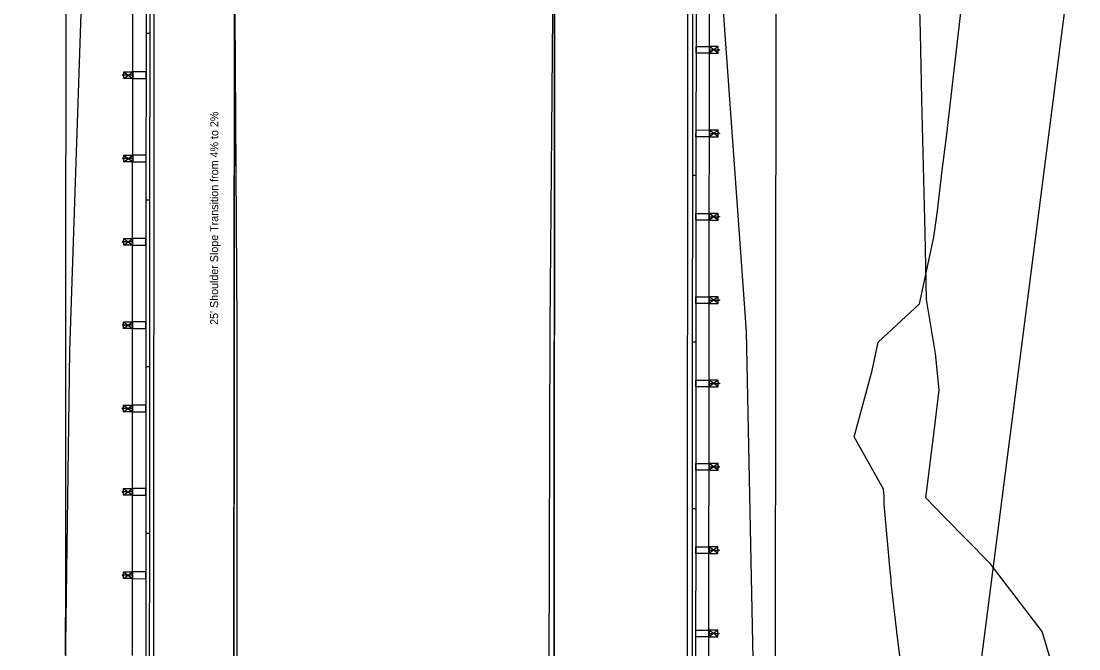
# Model space of a CAD drawing. Extents: x 18543285 to 18543485, y 7434209 to 7435438.
# Drawn here: x 18543356.7 to 18543436, y 7434626.5 to 7434673.5 of the extents above; entities that cross this region are included whole.
import ezdxf

# ---------------------------------------------------------------- set-up
doc = ezdxf.new("R2010")
doc.units = 0
for name, color, linetype in [('_CIVIL_CONSTRUCTION', 7, 'Continuous'), ('Contours Major', 7, 'Continuous'), ('Dimensions', 7, 'Continuous'), ('Draft_1', 7, 'Continuous'), ('EdgeUnpaved', 7, 'Continuous'), ('EXT_SNP', 7, 'Continuous'), ('MeshTop', 7, 'Continuous'), ('Sawcut', 7, 'Continuous'), ('Terrain', 7, 'Continuous'), ('TL_ForeSlope', 7, 'Continuous'), ('TL_Grading', 7, 'Continuous'), ('TL_GroundIntercept', 7, 'Continuous')]:
    doc.layers.add(name, color=color, linetype=linetype)

msp = doc.modelspace()

# ---------------------------------------------------------------- linework, layer by layer
at = {"layer": '_CIVIL_CONSTRUCTION'}
for p, q in [((18543372.717, 7434758.131), (18543372.483, 7434398.131)), ((18543396.702, 7434735.024), (18543396.468, 7434375.024)), ((18543396.468, 7434375.024), (18543442.702, 7434734.994))]:
    msp.add_line(p, q, dxfattribs=at)
at = {"layer": 'Contours Major'}
for p, q in [((18543366.494, 7434414.304), (18543366.721, 7434764.553)), ((18543406.503, 7434428.685), (18543406.706, 7434741.433))]:
    msp.add_line(p, q, dxfattribs=at)
for points in [[(18543365.016, 7434626.011), (18543365.02, 7434631.761), (18543365.02, 7434632.261), (18543365.024, 7434638.011), (18543365.024, 7434638.511), (18543365.056, 7434688.511), (18543365.06, 7434694.261), (18543365.06, 7434694.761), (18543365.065, 7434700.511), (18543365.064, 7434701.011), (18543365.085, 7434732.261), (18543365.086, 7434734.886), (18543365.101, 7434758.323), (18543365.101, 7434758.823), (18543365.134, 7434759.303)], [(18543410.073, 7434448.682), (18543409.662, 7434459.133), (18543409.398, 7434465.002), (18543408.155, 7434496.603), (18543408.262, 7434502.429), (18543408.242, 7434502.929), (18543408.171, 7434508.639), (18543408.179, 7434521.639), (18543408.182, 7434527.389), (18543408.183, 7434527.889), (18543408.268, 7434659.139), (18543408.272, 7434664.889), (18543408.272, 7434665.389), (18543408.301, 7434709.139), (18543408.303, 7434711.764), (18543408.305, 7434714.889), (18543408.305, 7434715.389), (18543408.307, 7434718.014), (18543408.316, 7434732.076), (18543408.317, 7434732.576), (18543408.317, 7434733.639), (18543408.318, 7434735.701), (18543408.286, 7434736.181), (18543408.292, 7434745.597)]]:
    msp.add_lwpolyline(points, dxfattribs=at)
at = {"layer": 'Dimensions'}
for p, q in [((18543424.09, 7434672.685), (18543423.973, 7434677.682)), ((18543424.208, 7434667.687), (18543424.09, 7434672.685)), ((18543424.325, 7434662.69), (18543424.208, 7434667.687)), ((18543424.443, 7434657.692), (18543424.325, 7434662.69)), ((18543424.56, 7434652.695), (18543424.443, 7434657.692)), ((18543425.23, 7434648.632), (18543424.56, 7434652.695)), ((18543425.51, 7434645.922), (18543425.23, 7434648.632)), ((18543425.115, 7434642.783), (18543425.51, 7434645.922)), ((18543424.49, 7434637.824), (18543425.115, 7434642.783)), ((18543425.885, 7434636.402), (18543424.49, 7434637.824)), ((18543429.322, 7434632.897), (18543425.885, 7434636.402)), ((18543433.233, 7434627.79), (18543429.322, 7434632.897)), ((18543434.64, 7434623.023), (18543433.233, 7434627.79))]:
    msp.add_line(p, q, dxfattribs=at)
at = {"layer": 'Draft_1'}
for points in [[(18543384.77, 7434781.083), (18543372.9, 7434787.863), (18543372.96, 7434740.606), (18543372.8, 7434701.585), (18543372.37, 7434691.21), (18543372.62, 7434685.7), (18543372.86, 7434650.748), (18543372.86, 7434601.252), (18543372.78, 7434549.829), (18543372.8, 7434512.681), (18543372.38, 7434462.376), (18543372.39, 7434412.042), (18543372.69, 7434360.71), (18543372.51, 7434311.653), (18543372.28, 7434264.026), (18543372.36, 7434218.914)], [(18543384.77, 7434781.083), (18543396.87, 7434774.205), (18543396.35, 7434740.197), (18543396.71, 7434700.664), (18543396.63, 7434690.476), (18543396.62, 7434685.792), (18543396.31, 7434650.659), (18543396.17, 7434599.128), (18543396.23, 7434549.104), (18543396.51, 7434511.985), (18543396.08, 7434463.739), (18543396.34, 7434410.307), (18543396.46, 7434361.391), (18543396, 7434310.756), (18543396.3, 7434264.052), (18543396.31, 7434218.783)]]:
    msp.add_lwpolyline(points, dxfattribs=at)
at = {"layer": 'EdgeUnpaved'}
for points in [[(18543366.95, 7434783.457), (18543367.08, 7434760.542), (18543365.95, 7434740.647), (18543362.08, 7434701.65), (18543360.3, 7434648.83), (18543359.65, 7434601.121), (18543356.68, 7434548.03), (18543360.21, 7434529.205), (18543361.5, 7434513.228), (18543365.09, 7434461.857), (18543364.63, 7434411.718), (18543364.49, 7434411.599), (18543365.08, 7434359.945), (18543365.18, 7434311.057), (18543365.28, 7434264.086), (18543364.89, 7434219.782)], [(18543403.57, 7434766.239), (18543404.16, 7434742.83), (18543404.19, 7434741.424), (18543407.36, 7434701.476), (18543411.03, 7434650.284), (18543412.11, 7434597.502), (18543415.34, 7434550.136), (18543409.98, 7434511.216), (18543406.99, 7434484.053), (18543407.7, 7434463.358), (18543406.85, 7434409.394), (18543406.22, 7434360.833), (18543406.88, 7434310.123), (18543406.41, 7434263.79), (18543406.74, 7434218.275)]]:
    msp.add_lwpolyline(points, dxfattribs=at)
at = {"layer": 'EXT_SNP'}
msp.add_lwpolyline([(18543366.95, 7434783.457), (18543367.08, 7434760.542), (18543365.95, 7434740.647), (18543362.08, 7434701.65), (18543360.3, 7434648.83), (18543359.65, 7434601.121), (18543356.68, 7434548.03), (18543360.21, 7434529.205), (18543361.5, 7434513.228), (18543365.09, 7434461.857), (18543364.63, 7434411.718), (18543364.49, 7434411.599), (18543365.08, 7434359.945), (18543365.18, 7434311.057), (18543365.28, 7434264.086), (18543364.89, 7434219.782)], dxfattribs=at)
at = {"layer": 'MeshTop'}
for points in [[(18543360.016, 7434626.014), (18543360.02, 7434631.761), (18543360.02, 7434632.262), (18543360.024, 7434638.011), (18543360.024, 7434638.512), (18543360.056, 7434688.514), (18543360.06, 7434694.261), (18543360.06, 7434694.762), (18543360.065, 7434700.511), (18543360.064, 7434701.011), (18543360.085, 7434732.264), (18543360.086, 7434734.889), (18543360.101, 7434758.323), (18543360.101, 7434758.996), (18543360.135, 7434759.477)], [(18543360.016, 7434626.014), (18543360.02, 7434631.761), (18543360.02, 7434632.262), (18543360.024, 7434638.011), (18543360.024, 7434638.512), (18543360.056, 7434688.514), (18543360.06, 7434694.261), (18543360.06, 7434694.762), (18543360.065, 7434700.511), (18543360.064, 7434701.011), (18543360.085, 7434732.264), (18543360.086, 7434734.889), (18543360.101, 7434758.323), (18543360.101, 7434758.996), (18543360.135, 7434759.477)], [(18543360.016, 7434626.014), (18543360.02, 7434631.761), (18543360.02, 7434632.262), (18543360.024, 7434638.011), (18543360.024, 7434638.512), (18543360.056, 7434688.514), (18543360.06, 7434694.261), (18543360.06, 7434694.762), (18543360.065, 7434700.511), (18543360.064, 7434701.011), (18543360.085, 7434732.264), (18543360.086, 7434734.889), (18543360.101, 7434758.323), (18543360.101, 7434758.996), (18543360.135, 7434759.477)], [(18543415.073, 7434448.779), (18543414.657, 7434459.344), (18543414.394, 7434465.213), (18543413.157, 7434496.655), (18543413.264, 7434502.482), (18543413.241, 7434503.058), (18543413.171, 7434508.669), (18543413.179, 7434521.636), (18543413.182, 7434527.383), (18543413.183, 7434527.883), (18543413.268, 7434659.136), (18543413.272, 7434664.883), (18543413.272, 7434665.383), (18543413.301, 7434709.136), (18543413.303, 7434711.76), (18543413.305, 7434714.882), (18543413.305, 7434715.384), (18543413.307, 7434718.011), (18543413.316, 7434732.07), (18543413.317, 7434732.572), (18543413.317, 7434733.637), (18543413.318, 7434735.868), (18543413.286, 7434736.347), (18543413.292, 7434745.594)], [(18543415.073, 7434448.779), (18543414.657, 7434459.344), (18543414.394, 7434465.213), (18543413.157, 7434496.655), (18543413.264, 7434502.482), (18543413.241, 7434503.058), (18543413.171, 7434508.669), (18543413.179, 7434521.636), (18543413.182, 7434527.383), (18543413.183, 7434527.883), (18543413.268, 7434659.136), (18543413.272, 7434664.883), (18543413.272, 7434665.383), (18543413.301, 7434709.136), (18543413.303, 7434711.76), (18543413.305, 7434714.882), (18543413.305, 7434715.384), (18543413.307, 7434718.011), (18543413.316, 7434732.07), (18543413.317, 7434732.572), (18543413.317, 7434733.637), (18543413.318, 7434735.868), (18543413.286, 7434736.347), (18543413.292, 7434745.594)]]:
    msp.add_lwpolyline(points, dxfattribs=at)
at = {"layer": 'Sawcut'}
msp.add_lwpolyline([(18543368.55, 7434414.302), (18543372.494, 7434414.3), (18543372.663, 7434674.434), (18543396.663, 7434674.418), (18543396.486, 7434402.372), (18543399.487, 7434402.37)], dxfattribs=at)
at = {"layer": 'TL_ForeSlope'}
for p, q in [((18543372.494, 7434414.3), (18543372.663, 7434674.434)), ((18543396.486, 7434402.372), (18543396.663, 7434674.418))]:
    msp.add_line(p, q, dxfattribs=at)
at = {"layer": 'TL_Grading'}
for p, q in [((18543366.055, 7434685.135), (18543366.047, 7434672.635)), ((18543366.326, 7434685.135), (18543366.318, 7434672.635)), ((18543407.007, 7434674.515), (18543406.999, 7434662.015)), ((18543407.277, 7434674.515), (18543407.269, 7434662.015)), ((18543366.047, 7434672.635), (18543366.039, 7434660.135)), ((18543366.318, 7434672.635), (18543366.047, 7434672.635)), ((18543366.318, 7434672.635), (18543366.047, 7434672.635)), ((18543366.318, 7434672.635), (18543366.309, 7434660.135)), ((18543407.275, 7434671.139), (18543407.276, 7434671.64)), ((18543407.276, 7434671.64), (18543408.276, 7434671.639)), ((18543408.276, 7434671.639), (18543408.276, 7434671.139)), ((18543408.943, 7434671.639), (18543408.276, 7434671.139)), ((18543408.943, 7434671.139), (18543408.276, 7434671.639)), ((18543408.276, 7434671.389), (18543408.943, 7434671.389)), ((18543409.04, 7434671.388), (18543409.047, 7434671.388)), ((18543408.276, 7434671.139), (18543407.275, 7434671.139)), ((18543364.377, 7434669.761), (18543365.044, 7434669.261)), ((18543364.377, 7434669.261), (18543365.044, 7434669.761)), ((18543365.044, 7434669.761), (18543365.044, 7434669.261)), ((18543366.045, 7434669.76), (18543365.044, 7434669.761)), ((18543366.045, 7434669.26), (18543366.045, 7434669.76)), ((18543364.28, 7434669.512), (18543364.273, 7434669.512)), ((18543365.044, 7434669.511), (18543364.377, 7434669.511)), ((18543365.044, 7434669.261), (18543366.045, 7434669.26)), ((18543407.271, 7434664.889), (18543407.272, 7434665.39)), ((18543408.272, 7434664.889), (18543407.271, 7434664.889)), ((18543407.272, 7434665.39), (18543408.272, 7434665.389)), ((18543408.272, 7434665.389), (18543408.272, 7434664.889)), ((18543408.939, 7434665.389), (18543408.272, 7434664.889)), ((18543408.939, 7434664.889), (18543408.272, 7434665.389)), ((18543408.272, 7434665.139), (18543408.939, 7434665.139)), ((18543409.036, 7434665.138), (18543409.043, 7434665.138)), ((18543364.276, 7434663.262), (18543364.269, 7434663.262)), ((18543364.373, 7434663.511), (18543365.04, 7434663.011)), ((18543364.373, 7434663.011), (18543365.04, 7434663.511)), ((18543365.04, 7434663.261), (18543364.373, 7434663.261)), ((18543365.04, 7434663.511), (18543365.04, 7434663.011)), ((18543366.041, 7434663.51), (18543365.04, 7434663.511)), ((18543366.04, 7434663.01), (18543366.041, 7434663.51)), ((18543365.04, 7434663.011), (18543366.04, 7434663.01)), ((18543406.999, 7434662.015), (18543406.99, 7434649.515)), ((18543406.999, 7434662.015), (18543407.269, 7434662.015)), ((18543406.999, 7434662.015), (18543407.269, 7434662.015)), ((18543407.269, 7434662.015), (18543407.261, 7434649.515)), ((18543366.039, 7434660.135), (18543366.03, 7434647.635)), ((18543366.309, 7434660.135), (18543366.039, 7434660.135)), ((18543366.309, 7434660.135), (18543366.039, 7434660.135)), ((18543366.309, 7434660.135), (18543366.301, 7434647.635)), ((18543407.267, 7434658.639), (18543407.267, 7434659.14)), ((18543407.267, 7434659.14), (18543408.268, 7434659.139)), ((18543408.268, 7434658.639), (18543407.267, 7434658.639)), ((18543408.268, 7434659.139), (18543408.268, 7434658.639)), ((18543408.935, 7434659.139), (18543408.268, 7434658.639)), ((18543408.935, 7434658.639), (18543408.268, 7434659.139)), ((18543408.268, 7434658.889), (18543408.935, 7434658.889)), ((18543409.032, 7434658.888), (18543409.039, 7434658.888)), ((18543364.272, 7434657.012), (18543364.265, 7434657.012)), ((18543364.369, 7434657.261), (18543365.036, 7434656.761)), ((18543364.369, 7434656.761), (18543365.036, 7434657.261)), ((18543365.036, 7434657.011), (18543364.369, 7434657.011)), ((18543365.036, 7434657.261), (18543365.036, 7434656.761)), ((18543366.037, 7434657.26), (18543365.036, 7434657.261)), ((18543366.036, 7434656.76), (18543366.037, 7434657.26)), ((18543365.036, 7434656.761), (18543366.036, 7434656.76)), ((18543407.263, 7434652.389), (18543407.263, 7434652.89)), ((18543407.263, 7434652.89), (18543408.264, 7434652.889)), ((18543408.264, 7434652.389), (18543407.263, 7434652.389)), ((18543408.264, 7434652.889), (18543408.264, 7434652.389)), ((18543408.931, 7434652.889), (18543408.264, 7434652.389)), ((18543408.931, 7434652.389), (18543408.264, 7434652.889)), ((18543408.264, 7434652.639), (18543408.931, 7434652.639)), ((18543409.028, 7434652.638), (18543409.035, 7434652.638)), ((18543364.268, 7434650.762), (18543364.261, 7434650.762)), ((18543364.365, 7434651.011), (18543365.032, 7434650.511)), ((18543364.365, 7434650.511), (18543365.032, 7434651.011)), ((18543365.032, 7434650.761), (18543364.365, 7434650.761)), ((18543365.032, 7434651.011), (18543365.032, 7434650.511)), ((18543366.033, 7434651.01), (18543365.032, 7434651.011)), ((18543366.032, 7434650.51), (18543366.033, 7434651.01)), ((18543365.032, 7434650.511), (18543366.032, 7434650.51)), ((18543406.99, 7434649.515), (18543406.982, 7434637.015)), ((18543406.99, 7434649.515), (18543407.261, 7434649.515)), ((18543406.99, 7434649.515), (18543407.261, 7434649.515)), ((18543407.261, 7434649.515), (18543407.253, 7434637.015)), ((18543366.03, 7434647.635), (18543366.022, 7434635.135)), ((18543366.301, 7434647.635), (18543366.03, 7434647.635)), ((18543366.301, 7434647.635), (18543366.03, 7434647.635)), ((18543366.301, 7434647.635), (18543366.293, 7434635.135)), ((18543407.259, 7434646.139), (18543407.259, 7434646.64)), ((18543407.259, 7434646.64), (18543408.26, 7434646.639)), ((18543408.26, 7434646.639), (18543408.26, 7434646.139)), ((18543408.927, 7434646.639), (18543408.26, 7434646.139)), ((18543408.927, 7434646.139), (18543408.26, 7434646.639)), ((18543408.26, 7434646.139), (18543407.259, 7434646.139)), ((18543408.26, 7434646.389), (18543408.927, 7434646.389)), ((18543409.024, 7434646.388), (18543409.031, 7434646.388)), ((18543364.264, 7434644.512), (18543364.257, 7434644.512)), ((18543364.361, 7434644.761), (18543365.027, 7434644.261)), ((18543364.361, 7434644.261), (18543365.028, 7434644.761)), ((18543365.028, 7434644.511), (18543364.361, 7434644.511)), ((18543365.028, 7434644.761), (18543365.027, 7434644.261)), ((18543365.027, 7434644.261), (18543366.028, 7434644.26)), ((18543366.029, 7434644.76), (18543365.028, 7434644.761)), ((18543366.028, 7434644.26), (18543366.029, 7434644.76)), ((18543407.255, 7434639.889), (18543407.255, 7434640.39)), ((18543407.255, 7434640.39), (18543408.256, 7434640.389)), ((18543408.256, 7434640.389), (18543408.256, 7434639.889)), ((18543408.923, 7434640.389), (18543408.256, 7434639.889)), ((18543408.922, 7434639.889), (18543408.256, 7434640.389)), ((18543408.256, 7434639.889), (18543407.255, 7434639.889)), ((18543408.256, 7434640.139), (18543408.923, 7434640.139)), ((18543409.02, 7434640.138), (18543409.027, 7434640.138)), ((18543364.26, 7434638.262), (18543364.253, 7434638.262)), ((18543364.357, 7434638.511), (18543365.023, 7434638.011)), ((18543364.357, 7434638.011), (18543365.024, 7434638.511)), ((18543365.024, 7434638.261), (18543364.357, 7434638.261)), ((18543365.024, 7434638.511), (18543365.023, 7434638.011)), ((18543365.023, 7434638.011), (18543366.024, 7434638.01)), ((18543366.025, 7434638.51), (18543365.024, 7434638.511)), ((18543366.024, 7434638.01), (18543366.025, 7434638.51)), ((18543406.982, 7434637.015), (18543406.974, 7434624.515)), ((18543406.982, 7434637.015), (18543407.253, 7434637.015)), ((18543406.982, 7434637.015), (18543407.253, 7434637.015)), ((18543407.253, 7434637.015), (18543407.245, 7434624.515)), ((18543366.022, 7434635.135), (18543366.014, 7434622.635)), ((18543366.293, 7434635.135), (18543366.022, 7434635.135)), ((18543366.293, 7434635.135), (18543366.022, 7434635.135)), ((18543366.293, 7434635.135), (18543366.285, 7434622.635)), ((18543407.251, 7434633.639), (18543407.251, 7434634.14)), ((18543407.251, 7434634.14), (18543408.252, 7434634.139)), ((18543408.252, 7434634.139), (18543408.252, 7434633.639)), ((18543408.919, 7434634.139), (18543408.252, 7434633.639)), ((18543408.918, 7434633.639), (18543408.252, 7434634.139)), ((18543408.252, 7434633.639), (18543407.251, 7434633.639)), ((18543408.252, 7434633.889), (18543408.919, 7434633.889)), ((18543409.016, 7434633.888), (18543409.023, 7434633.888)), ((18543364.256, 7434632.012), (18543364.249, 7434632.012)), ((18543364.353, 7434632.261), (18543365.019, 7434631.761)), ((18543364.353, 7434631.761), (18543365.02, 7434632.261)), ((18543365.019, 7434632.011), (18543364.353, 7434632.011)), ((18543365.02, 7434632.261), (18543365.019, 7434631.761)), ((18543365.019, 7434631.761), (18543366.02, 7434631.76)), ((18543366.02, 7434632.26), (18543365.02, 7434632.261)), ((18543366.02, 7434631.76), (18543366.02, 7434632.26)), ((18543407.247, 7434627.389), (18543407.247, 7434627.89)), ((18543407.247, 7434627.89), (18543408.248, 7434627.889)), ((18543408.248, 7434627.889), (18543408.248, 7434627.389)), ((18543408.915, 7434627.889), (18543408.248, 7434627.389)), ((18543408.914, 7434627.389), (18543408.248, 7434627.889)), ((18543408.248, 7434627.639), (18543408.915, 7434627.639)), ((18543409.012, 7434627.638), (18543409.019, 7434627.638)), ((18543408.248, 7434627.389), (18543407.247, 7434627.389))]:
    msp.add_line(p, q, dxfattribs=at)
for points in [[(18543408.276, 7434671.639), (18543408.276, 7434671.139), (18543408.943, 7434671.139), (18543408.943, 7434671.639)], [(18543365.044, 7434669.761), (18543365.044, 7434669.261), (18543364.377, 7434669.261), (18543364.377, 7434669.761)], [(18543408.272, 7434665.389), (18543408.272, 7434664.889), (18543408.939, 7434664.889), (18543408.939, 7434665.389)], [(18543365.04, 7434663.511), (18543365.04, 7434663.011), (18543364.373, 7434663.011), (18543364.373, 7434663.511)], [(18543408.268, 7434659.139), (18543408.268, 7434658.639), (18543408.935, 7434658.639), (18543408.935, 7434659.139)], [(18543365.036, 7434657.261), (18543365.036, 7434656.761), (18543364.369, 7434656.761), (18543364.369, 7434657.261)], [(18543408.264, 7434652.889), (18543408.264, 7434652.389), (18543408.931, 7434652.389), (18543408.931, 7434652.889)], [(18543365.032, 7434651.011), (18543365.032, 7434650.511), (18543364.365, 7434650.511), (18543364.365, 7434651.011)], [(18543408.26, 7434646.639), (18543408.26, 7434646.139), (18543408.927, 7434646.139), (18543408.927, 7434646.639)], [(18543365.028, 7434644.761), (18543365.027, 7434644.261), (18543364.361, 7434644.261), (18543364.361, 7434644.761)], [(18543408.256, 7434640.389), (18543408.256, 7434639.889), (18543408.922, 7434639.889), (18543408.923, 7434640.389)], [(18543365.024, 7434638.511), (18543365.023, 7434638.011), (18543364.357, 7434638.011), (18543364.357, 7434638.511)], [(18543408.252, 7434634.139), (18543408.252, 7434633.639), (18543408.918, 7434633.639), (18543408.919, 7434634.139)], [(18543365.02, 7434632.261), (18543365.019, 7434631.761), (18543364.353, 7434631.761), (18543364.353, 7434632.261)], [(18543408.248, 7434627.889), (18543408.248, 7434627.389), (18543408.914, 7434627.389), (18543408.915, 7434627.889)]]:
    msp.add_lwpolyline(points, close=True, dxfattribs=at)
for points in [[(18543408.943, 7434671.422), (18543408.986, 7434671.422), (18543408.986, 7434671.355), (18543408.943, 7434671.355)], [(18543408.986, 7434671.408), (18543409.04, 7434671.408), (18543409.04, 7434671.369), (18543408.986, 7434671.369)], [(18543364.334, 7434669.531), (18543364.28, 7434669.531), (18543364.28, 7434669.492), (18543364.334, 7434669.492)], [(18543364.377, 7434669.545), (18543364.334, 7434669.545), (18543364.334, 7434669.478), (18543364.377, 7434669.478)], [(18543408.939, 7434665.172), (18543408.982, 7434665.172), (18543408.982, 7434665.105), (18543408.939, 7434665.105)], [(18543408.982, 7434665.158), (18543409.036, 7434665.158), (18543409.036, 7434665.119), (18543408.982, 7434665.119)], [(18543364.33, 7434663.281), (18543364.276, 7434663.281), (18543364.276, 7434663.242), (18543364.33, 7434663.242)], [(18543364.373, 7434663.295), (18543364.33, 7434663.295), (18543364.33, 7434663.228), (18543364.373, 7434663.228)], [(18543408.935, 7434658.922), (18543408.978, 7434658.922), (18543408.978, 7434658.855), (18543408.935, 7434658.855)], [(18543408.978, 7434658.908), (18543409.032, 7434658.908), (18543409.032, 7434658.869), (18543408.978, 7434658.869)], [(18543364.326, 7434657.031), (18543364.272, 7434657.031), (18543364.272, 7434656.992), (18543364.326, 7434656.992)], [(18543364.369, 7434657.045), (18543364.326, 7434657.045), (18543364.326, 7434656.978), (18543364.369, 7434656.978)], [(18543408.931, 7434652.672), (18543408.974, 7434652.672), (18543408.974, 7434652.605), (18543408.931, 7434652.605)], [(18543408.974, 7434652.658), (18543409.028, 7434652.658), (18543409.028, 7434652.619), (18543408.974, 7434652.619)], [(18543364.322, 7434650.781), (18543364.268, 7434650.781), (18543364.268, 7434650.742), (18543364.322, 7434650.742)], [(18543364.365, 7434650.795), (18543364.322, 7434650.795), (18543364.322, 7434650.728), (18543364.365, 7434650.728)], [(18543408.927, 7434646.422), (18543408.97, 7434646.422), (18543408.97, 7434646.355), (18543408.927, 7434646.355)], [(18543408.97, 7434646.408), (18543409.024, 7434646.408), (18543409.024, 7434646.369), (18543408.97, 7434646.369)], [(18543364.318, 7434644.531), (18543364.264, 7434644.531), (18543364.264, 7434644.492), (18543364.318, 7434644.492)], [(18543364.361, 7434644.545), (18543364.318, 7434644.545), (18543364.318, 7434644.478), (18543364.361, 7434644.478)], [(18543408.923, 7434640.172), (18543408.966, 7434640.172), (18543408.966, 7434640.105), (18543408.923, 7434640.105)], [(18543408.966, 7434640.158), (18543409.02, 7434640.158), (18543409.02, 7434640.119), (18543408.966, 7434640.119)], [(18543364.314, 7434638.281), (18543364.26, 7434638.281), (18543364.26, 7434638.242), (18543364.314, 7434638.242)], [(18543364.357, 7434638.295), (18543364.314, 7434638.295), (18543364.314, 7434638.228), (18543364.357, 7434638.228)], [(18543408.919, 7434633.922), (18543408.962, 7434633.922), (18543408.962, 7434633.855), (18543408.919, 7434633.855)], [(18543408.962, 7434633.908), (18543409.016, 7434633.908), (18543409.016, 7434633.869), (18543408.962, 7434633.869)], [(18543364.31, 7434632.031), (18543364.256, 7434632.031), (18543364.256, 7434631.992), (18543364.31, 7434631.992)], [(18543364.353, 7434632.045), (18543364.31, 7434632.045), (18543364.31, 7434631.978), (18543364.353, 7434631.978)], [(18543408.915, 7434627.672), (18543408.958, 7434627.672), (18543408.958, 7434627.605), (18543408.915, 7434627.605)], [(18543408.958, 7434627.658), (18543409.012, 7434627.658), (18543409.012, 7434627.619), (18543408.958, 7434627.619)]]:
    msp.add_lwpolyline(points, dxfattribs=at)
at = {"layer": 'TL_GroundIntercept'}
msp.add_lwpolyline([(18543422.557, 7434625.974), (18543422.39, 7434627.355), (18543421.894, 7434631.453), (18543421.891, 7434631.721), (18543421.826, 7434632.356), (18543421.379, 7434637.356), (18543421.371, 7434637.974), (18543421.318, 7434638.474), (18543419.119, 7434642.397), (18543420.478, 7434647.356), (18543420.931, 7434649.499), (18543424.025, 7434652.354), (18543425.112, 7434657.353), (18543425.341, 7434659.128), (18543425.73, 7434662.353), (18543426.047, 7434664.875), (18543427.154, 7434674.398)], dxfattribs=at)

# ---------------------------------------------------------------- texts
at = {"layer": 'Terrain'}
msp.add_text("25' Shoulder Slope Transition from 4% to 2%", height=0.6, rotation=89.96279, dxfattribs=at).set_placement((18543371.446, 7434650.781))

doc.saveas('drawing.dxf')
